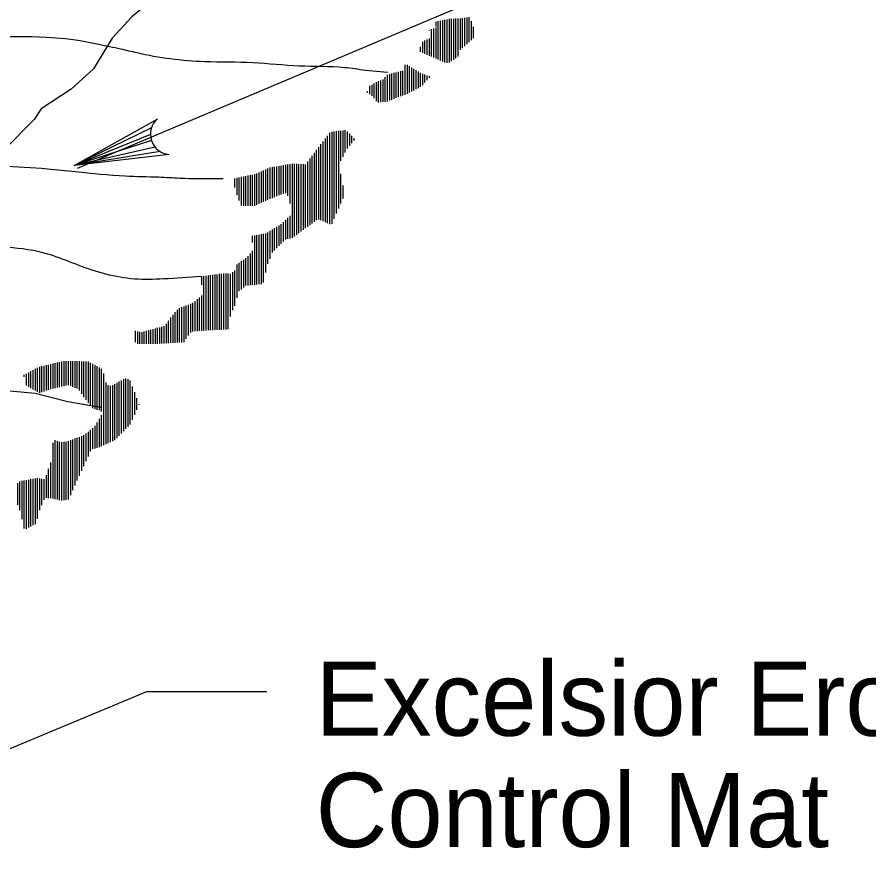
# Model space of a CAD drawing. Extents: x 1083.1 to 1117.1, y 719.4 to 741.4.
# Drawn here: x 1107.903 to 1109.509, y 721.997 to 723.597 of the extents above; entities that cross this region are included whole.
import ezdxf

# ---------------------------------------------------------------- set-up
doc = ezdxf.new("R2010")
doc.units = 0
doc.layers.add('ST_Details', color=7, linetype='Continuous')
doc.layers.add('ST_Text', color=7, linetype='Continuous')

msp = doc.modelspace()

# ---------------------------------------------------------------- linework, layer by layer
at = {"layer": 'ST_Details'}
for p, q in [((1108.6886, 723.5872), (1108.6886, 723.5875)), ((1108.6928, 723.5796), (1108.6928, 723.5885)), ((1108.6969, 723.5175), (1108.6969, 723.5894)), ((1108.7011, 723.5156), (1108.7011, 723.5904)), ((1108.7053, 723.5138), (1108.7053, 723.5913)), ((1108.7094, 723.512), (1108.7094, 723.5922)), ((1108.7136, 723.511), (1108.7136, 723.5931)), ((1108.7178, 723.512), (1108.7178, 723.594)), ((1108.7219, 723.514), (1108.7219, 723.5942)), ((1108.7261, 723.517), (1108.7261, 723.5944)), ((1108.7303, 723.5202), (1108.7303, 723.5945)), ((1108.7344, 723.5232), (1108.7344, 723.5948)), ((1108.7386, 723.5354), (1108.7386, 723.595)), ((1108.7428, 723.539), (1108.7428, 723.5955)), ((1108.7469, 723.5428), (1108.7469, 723.596)), ((1108.7511, 723.5465), (1108.7511, 723.5965)), ((1108.7553, 723.5503), (1108.7553, 723.597)), ((1108.7594, 723.554), (1108.7594, 723.5899)), ((1108.6803, 723.5721), (1108.6803, 723.5728)), ((1108.6844, 723.5229), (1108.6844, 723.5744)), ((1108.6886, 723.521), (1108.6886, 723.576)), ((1108.6928, 723.5192), (1108.6928, 723.5777)), ((1108.7636, 723.5578), (1108.7636, 723.5789)), ((1108.6719, 723.5283), (1108.6719, 723.5532)), ((1108.6761, 723.5265), (1108.6761, 723.555)), ((1108.6803, 723.5246), (1108.6803, 723.557)), ((1108.6636, 723.5319), (1108.6636, 723.5415)), ((1108.6678, 723.5301), (1108.6678, 723.5505)), ((1108.7386, 723.5263), (1108.7386, 723.5263)), ((1108.6345, 723.4511), (1108.6345, 723.5072)), ((1108.6386, 723.4526), (1108.6386, 723.5076)), ((1108.6428, 723.4546), (1108.6428, 723.505)), ((1108.5595, 723.4974), (1108.601, 723.4935)), ((1108.6012, 723.4385), (1108.6012, 723.4886)), ((1108.6053, 723.44), (1108.6053, 723.4898)), ((1108.6095, 723.4416), (1108.6095, 723.4908)), ((1108.6137, 723.4433), (1108.6137, 723.492)), ((1108.6178, 723.4449), (1108.6178, 723.493)), ((1108.622, 723.4465), (1108.622, 723.4941)), ((1108.6262, 723.448), (1108.6262, 723.4953)), ((1108.6303, 723.4495), (1108.6303, 723.4963)), ((1108.6469, 723.457), (1108.6469, 723.5025)), ((1108.6511, 723.4591), (1108.6511, 723.5)), ((1108.6553, 723.4615), (1108.6553, 723.4974)), ((1108.6594, 723.4636), (1108.6594, 723.4948)), ((1108.6636, 723.466), (1108.6636, 723.4922)), ((1108.6678, 723.4693), (1108.6678, 723.4905)), ((1108.6719, 723.4738), (1108.6719, 723.4889)), ((1108.6761, 723.4784), (1108.6761, 723.4874)), ((1108.5762, 723.4445), (1108.5762, 723.4721)), ((1108.5803, 723.4388), (1108.5803, 723.4745)), ((1108.5845, 723.4365), (1108.5845, 723.4763)), ((1108.5887, 723.437), (1108.5887, 723.478)), ((1108.5928, 723.4375), (1108.5928, 723.4796)), ((1108.597, 723.4379), (1108.597, 723.484)), ((1108.6803, 723.483), (1108.6803, 723.4858)), ((1108.5637, 723.455), (1108.5637, 723.4577)), ((1108.5678, 723.452), (1108.5678, 723.4675)), ((1108.572, 723.449), (1108.572, 723.4698)), ((1108.156, 723.3883), (1108.0104, 723.3178)), ((1108.1543, 723.376), (1108.0104, 723.3178)), ((1108.4925, 723.2071), (1108.4925, 723.3791)), ((1108.4967, 723.2078), (1108.4967, 723.3813)), ((1108.5008, 723.2173), (1108.5008, 723.3818)), ((1108.505, 723.2268), (1108.505, 723.3823)), ((1108.5092, 723.2363), (1108.5092, 723.3828)), ((1108.5133, 723.3262), (1108.5133, 723.3832)), ((1108.5175, 723.3341), (1108.5175, 723.3836)), ((1108.5217, 723.342), (1108.5217, 723.3841)), ((1108.5258, 723.3494), (1108.5258, 723.3815)), ((1108.53, 723.3545), (1108.53, 723.3775)), ((1108.1562, 723.3648), (1108.0104, 723.3178)), ((1108.48, 723.2127), (1108.48, 723.363)), ((1108.4842, 723.2108), (1108.4842, 723.3684)), ((1108.4883, 723.209), (1108.4883, 723.3738)), ((1108.5342, 723.3598), (1108.5342, 723.3734)), ((1108.5383, 723.365), (1108.5383, 723.3693)), ((1108.1633, 723.352), (1108.0104, 723.3178)), ((1108.1723, 723.344), (1108.0104, 723.3178)), ((1108.4675, 723.2144), (1108.4675, 723.3469)), ((1108.4717, 723.2156), (1108.4717, 723.3523)), ((1108.4758, 723.2144), (1108.4758, 723.3576)), ((1108.4551, 723.2052), (1108.4551, 723.3305)), ((1108.4592, 723.2082), (1108.4592, 723.336)), ((1108.4633, 723.2113), (1108.4633, 723.3415)), ((1108.3718, 723.2508), (1108.3718, 723.3102)), ((1108.3759, 723.2526), (1108.3759, 723.312)), ((1108.3801, 723.2545), (1108.3801, 723.3135)), ((1108.3843, 723.2562), (1108.3843, 723.3142)), ((1108.3884, 723.258), (1108.3884, 723.315)), ((1108.3926, 723.2599), (1108.3926, 723.3157)), ((1108.3968, 723.2616), (1108.3968, 723.3165)), ((1108.4009, 723.2628), (1108.4009, 723.3172)), ((1108.4051, 723.264), (1108.4051, 723.3179)), ((1108.4093, 723.2651), (1108.4093, 723.3186)), ((1108.4134, 723.2605), (1108.4134, 723.3194)), ((1108.4176, 723.2457), (1108.4176, 723.32)), ((1108.4218, 723.1811), (1108.4218, 723.3207)), ((1108.4259, 723.1838), (1108.4259, 723.3205)), ((1108.4301, 723.1868), (1108.4301, 723.3204)), ((1108.4343, 723.1899), (1108.4343, 723.3202)), ((1108.4384, 723.193), (1108.4384, 723.32)), ((1108.4426, 723.196), (1108.4426, 723.3199)), ((1108.4468, 723.1991), (1108.4468, 723.3197)), ((1108.4509, 723.2021), (1108.4509, 723.3251)), ((1108.3176, 723.2614), (1108.3176, 723.2942)), ((1108.3218, 723.2516), (1108.3218, 723.295)), ((1108.3259, 723.2419), (1108.3259, 723.2959)), ((1108.3301, 723.2412), (1108.3301, 723.2968)), ((1108.3343, 723.2412), (1108.3343, 723.2976)), ((1108.3384, 723.2413), (1108.3384, 723.2985)), ((1108.3426, 723.2413), (1108.3426, 723.2994)), ((1108.3468, 723.2413), (1108.3468, 723.3002)), ((1108.3509, 723.2416), (1108.3509, 723.3011)), ((1108.3551, 723.2435), (1108.3551, 723.3025)), ((1108.3593, 723.2453), (1108.3593, 723.3044)), ((1108.3634, 723.2471), (1108.3634, 723.3064)), ((1108.3676, 723.249), (1108.3676, 723.3082)), ((1108.5133, 723.2457), (1108.5133, 723.302)), ((1108.3134, 723.2762), (1108.3134, 723.2933)), ((1108.5175, 723.2552), (1108.5175, 723.28)), ((1108.4093, 723.1781), (1108.4093, 723.2148)), ((1108.4134, 723.1791), (1108.4134, 723.2189)), ((1108.4176, 723.1801), (1108.4176, 723.2229)), ((1108.3884, 723.1575), (1108.3884, 723.1993)), ((1108.3926, 723.1617), (1108.3926, 723.202)), ((1108.3968, 723.166), (1108.3968, 723.2045)), ((1108.4009, 723.1701), (1108.4009, 723.2071)), ((1108.4051, 723.1743), (1108.4051, 723.2108)), ((1108.3468, 723.1723), (1108.3468, 723.1848)), ((1108.3509, 723.0928), (1108.3509, 723.1855)), ((1108.3551, 723.0932), (1108.3551, 723.1863)), ((1108.3593, 723.0936), (1108.3593, 723.1871)), ((1108.3634, 723.094), (1108.3634, 723.1878)), ((1108.3676, 723.0971), (1108.3676, 723.1886)), ((1108.3718, 723.1155), (1108.3718, 723.1894)), ((1108.3759, 723.1321), (1108.3759, 723.1915)), ((1108.3801, 723.1418), (1108.3801, 723.1941)), ((1108.3843, 723.1534), (1108.3843, 723.1967)), ((1108.3426, 723.092), (1108.3426, 723.1516)), ((1108.3468, 723.0924), (1108.3468, 723.1569)), ((1108.3218, 723.0805), (1108.3218, 723.1338)), ((1108.3259, 723.084), (1108.3259, 723.137)), ((1108.3301, 723.0875), (1108.3301, 723.1399)), ((1108.3343, 723.091), (1108.3343, 723.1429)), ((1108.3384, 723.0915), (1108.3384, 723.1464)), ((1108.3134, 723.0532), (1108.3134, 723.1193)), ((1108.3176, 723.068), (1108.3176, 723.1307)), ((1108.2468, 723.1075), (1108.2468, 723.1077)), ((1108.251, 723.0923), (1108.251, 723.1083)), ((1108.2552, 723.0064), (1108.2552, 723.1089)), ((1108.2593, 723.0067), (1108.2593, 723.1095)), ((1108.2635, 723.0069), (1108.2635, 723.11)), ((1108.2677, 723.007), (1108.2677, 723.1106)), ((1108.2718, 723.0073), (1108.2718, 723.1111)), ((1108.276, 723.0075), (1108.276, 723.1118)), ((1108.2801, 723.0077), (1108.2801, 723.1123)), ((1108.2843, 723.0079), (1108.2843, 723.113)), ((1108.2884, 723.008), (1108.2884, 723.1135)), ((1108.2926, 723.0083), (1108.2926, 723.114)), ((1108.2968, 723.0085), (1108.2968, 723.1142)), ((1108.3009, 723.0087), (1108.3009, 723.1138)), ((1108.3051, 723.033), (1108.3051, 723.1133)), ((1108.3093, 723.0449), (1108.3093, 723.1163)), ((1108.251, 723.006), (1108.251, 723.0723)), ((1108.2218, 722.991), (1108.2218, 723.0535)), ((1108.226, 722.997), (1108.226, 723.0551)), ((1108.2302, 723.0029), (1108.2302, 723.0567)), ((1108.2343, 723.0046), (1108.2343, 723.0585)), ((1108.2385, 723.005), (1108.2385, 723.062)), ((1108.2427, 723.0054), (1108.2427, 723.0655)), ((1108.2468, 723.0057), (1108.2468, 723.0688)), ((1108.201, 722.9833), (1108.201, 723.0409)), ((1108.2052, 722.9835), (1108.2052, 723.0457)), ((1108.2093, 722.9837), (1108.2093, 723.0486)), ((1108.2135, 722.984), (1108.2135, 723.0502)), ((1108.2177, 722.9844), (1108.2177, 723.0519)), ((1108.1885, 722.9826), (1108.1885, 723.0249)), ((1108.1927, 722.9829), (1108.1927, 723.0309)), ((1108.1968, 722.983), (1108.1968, 723.036)), ((1108.126, 722.9842), (1108.126, 723.0057)), ((1108.1468, 722.9815), (1108.1468, 723.0057)), ((1108.151, 722.9815), (1108.151, 723.0068)), ((1108.1552, 722.9816), (1108.1552, 723.0079)), ((1108.1593, 722.9816), (1108.1593, 723.009)), ((1108.1635, 722.9816), (1108.1635, 723.01)), ((1108.1677, 722.9816), (1108.1677, 723.0112)), ((1108.1718, 722.9818), (1108.1718, 723.0123)), ((1108.176, 722.982), (1108.176, 723.0134)), ((1108.1802, 722.9822), (1108.1802, 723.0145)), ((1108.1843, 722.9824), (1108.1843, 723.0189)), ((1108.1302, 722.981), (1108.1302, 723.0047)), ((1108.1343, 722.981), (1108.1343, 723.0038)), ((1108.1385, 722.9812), (1108.1385, 723.0035)), ((1108.1427, 722.9813), (1108.1427, 723.0045)), ((1107.9581, 722.893), (1107.9581, 722.9409)), ((1107.9623, 722.8944), (1107.9623, 722.9419)), ((1107.9664, 722.8958), (1107.9664, 722.9429)), ((1107.9706, 722.8968), (1107.9706, 722.944)), ((1107.9748, 722.8978), (1107.9748, 722.945)), ((1107.9789, 722.8988), (1107.9789, 722.946)), ((1107.9831, 722.8997), (1107.9831, 722.947)), ((1107.9873, 722.9006), (1107.9873, 722.948)), ((1107.9914, 722.9016), (1107.9914, 722.9489)), ((1107.9956, 722.9026), (1107.9956, 722.9489)), ((1107.9998, 722.9035), (1107.9998, 722.9487)), ((1108.0039, 722.902), (1108.0039, 722.9486)), ((1108.0081, 722.9003), (1108.0081, 722.9485)), ((1108.0123, 722.8986), (1108.0123, 722.9485)), ((1108.0164, 722.897), (1108.0164, 722.9484)), ((1108.0206, 722.8933), (1108.0206, 722.9483)), ((1108.0248, 722.8871), (1108.0248, 722.9482)), ((1108.0289, 722.881), (1108.0289, 722.948)), ((1108.0331, 722.8755), (1108.0331, 722.948)), ((1108.0373, 722.8703), (1108.0373, 722.9477)), ((1108.0414, 722.8653), (1108.0414, 722.9455)), ((1108.0456, 722.8601), (1108.0456, 722.9433)), ((1108.0498, 722.8583), (1108.0498, 722.941)), ((1107.9207, 722.9027), (1107.9207, 722.9249)), ((1107.9248, 722.9003), (1107.9248, 722.9272)), ((1107.9289, 722.898), (1107.9289, 722.9295)), ((1107.9331, 722.8955), (1107.9331, 722.9317)), ((1107.9373, 722.8931), (1107.9373, 722.934)), ((1107.9414, 722.8908), (1107.9414, 722.9363)), ((1107.9456, 722.8888), (1107.9456, 722.9378)), ((1107.9498, 722.8901), (1107.9498, 722.9389)), ((1107.9539, 722.8915), (1107.9539, 722.9399)), ((1108.0539, 722.8571), (1108.0539, 722.9389)), ((1108.0581, 722.856), (1108.0581, 722.9366)), ((1108.0623, 722.8535), (1108.0623, 722.9344)), ((1108.0664, 722.7901), (1108.0664, 722.9254)), ((1107.9165, 722.9193), (1107.9165, 722.9227)), ((1108.0706, 722.7921), (1108.0706, 722.9086)), ((1108.0956, 722.808), (1108.0956, 722.91)), ((1108.0998, 722.8123), (1108.0998, 722.9123)), ((1108.1039, 722.8165), (1108.1039, 722.9146)), ((1108.108, 722.8208), (1108.108, 722.9161)), ((1108.1122, 722.8251), (1108.1122, 722.9146)), ((1108.1163, 722.8295), (1108.1163, 722.912)), ((1108.0748, 722.794), (1108.0748, 722.9036)), ((1108.0789, 722.796), (1108.0789, 722.902)), ((1108.0831, 722.7978), (1108.0831, 722.9032)), ((1108.0873, 722.7998), (1108.0873, 722.9055)), ((1108.0914, 722.8036), (1108.0914, 722.9078)), ((1108.1205, 722.8383), (1108.1205, 722.901)), ((1108.1247, 722.8475), (1108.1247, 722.8899)), ((1108.1288, 722.8567), (1108.1288, 722.8788)), ((1108.133, 722.866), (1108.133, 722.8678)), ((1108.0623, 722.7883), (1108.0623, 722.8465)), ((1108.0539, 722.785), (1108.0539, 722.8331)), ((1108.0581, 722.7863), (1108.0581, 722.8398)), ((1108.0331, 722.7812), (1108.0331, 722.8124)), ((1108.0373, 722.782), (1108.0373, 722.8156)), ((1108.0414, 722.7826), (1108.0414, 722.8189)), ((1108.0456, 722.7835), (1108.0456, 722.8221)), ((1108.0498, 722.7841), (1108.0498, 722.8265)), ((1107.9748, 722.6887), (1107.9748, 722.7995)), ((1107.9789, 722.6877), (1107.9789, 722.798)), ((1107.9831, 722.6866), (1107.9831, 722.7965)), ((1107.9914, 722.6865), (1107.9914, 722.7963)), ((1107.9956, 722.6872), (1107.9956, 722.7968)), ((1107.9998, 722.6879), (1107.9998, 722.798)), ((1108.0039, 722.696), (1108.0039, 722.7995)), ((1108.0081, 722.7052), (1108.0081, 722.801)), ((1108.0123, 722.7143), (1108.0123, 722.8025)), ((1108.0164, 722.7234), (1108.0164, 722.8041)), ((1108.0206, 722.7325), (1108.0206, 722.8056)), ((1108.0248, 722.7417), (1108.0248, 722.8071)), ((1108.0289, 722.7508), (1108.0289, 722.8091)), ((1107.9706, 722.6897), (1107.9706, 722.7945)), ((1107.9873, 722.6859), (1107.9873, 722.7959)), ((1108.0331, 722.7599), (1108.0331, 722.7812)), ((1108.0373, 722.769), (1108.0373, 722.782)), ((1108.0414, 722.7782), (1108.0414, 722.7826)), ((1107.9664, 722.6902), (1107.9664, 722.7575)), ((1107.9581, 722.6909), (1107.9581, 722.7336)), ((1107.9623, 722.6905), (1107.9623, 722.7455)), ((1107.904, 722.6777), (1107.904, 722.7183)), ((1107.9082, 722.6677), (1107.9082, 722.722)), ((1107.9123, 722.6504), (1107.9123, 722.7228)), ((1107.9165, 722.633), (1107.9165, 722.7235)), ((1107.9207, 722.6325), (1107.9207, 722.7244)), ((1107.9248, 722.6347), (1107.9248, 722.7251)), ((1107.9289, 722.637), (1107.9289, 722.7259)), ((1107.9331, 722.6392), (1107.9331, 722.7267)), ((1107.9373, 722.6414), (1107.9373, 722.7275)), ((1107.9414, 722.6514), (1107.9414, 722.7278)), ((1107.9456, 722.6674), (1107.9456, 722.7272)), ((1107.9498, 722.6772), (1107.9498, 722.7267)), ((1107.9539, 722.6869), (1107.9539, 722.726))]:
    msp.add_line(p, q, dxfattribs=at)
for points in [[(1108.8059, 724.3275), (1108.7346, 724.2872), (1108.6921, 724.2617), (1108.6701, 724.2321), (1108.6434, 724.1676), (1108.6131, 724.1284), (1108.5522, 724.0713), (1108.5, 723.9771), (1108.4597, 723.9105), (1108.3613, 723.851), (1108.3054, 723.7939), (1108.2514, 723.7272), (1108.1872, 723.6541), (1108.1193, 723.598), (1108.0823, 723.5578), (1108.0469, 723.4996), (1108.0046, 723.4615), (1107.9485, 723.4244), (1107.935, 723.4043), (1107.8775, 723.346)], [(1108.0168, 723.3126), (1108.9788, 723.719), (1109.2207, 723.719)], [(1108.1898, 723.3384), (1108.0104, 723.3178), (1108.168, 723.4058)], [(1108.06, 722.8614), (1107.9984, 722.8718), (1107.9367, 722.8875), (1107.8478, 722.8958)], [(1107.3588, 721.9968), (1108.1472, 722.3259), (1108.374, 722.3259)]]:
    msp.add_lwpolyline(points, dxfattribs=at)
msp.add_arc((1108.1924, 723.3765), 0.0382, 129.9568, 265.783, dxfattribs=at)
for points in [[(1105.4163, 723.7798), (1105.5138, 723.7736), (1105.5651, 723.7695), (1105.6233, 723.7611), (1105.7088, 723.7486), (1105.7463, 723.7466), (1105.8369, 723.7446), (1105.8626, 723.7426), (1105.9224, 723.7364), (1105.9891, 723.7333), (1106.0592, 723.7293), (1106.1652, 723.7231), (1106.2508, 723.7063), (1106.3108, 723.697), (1106.403, 723.6865), (1106.5466, 723.6805), (1106.6323, 723.6648), (1106.7382, 723.6618), (1106.8578, 723.6621), (1106.9621, 723.6549), (1107.0682, 723.6425), (1107.1555, 723.6236), (1107.2274, 723.6058), (1107.3283, 723.5922), (1107.4258, 723.5882), (1107.5472, 723.5842), (1107.6566, 723.5739), (1107.8498, 723.5605), (1107.9574, 723.5597), (1108.031, 723.5514), (1108.0568, 723.5461), (1108.0978, 723.5377), (1108.1285, 723.5304), (1108.2569, 723.5137), (1108.3474, 723.5118), (1108.4348, 723.5056), (1108.5202, 723.5026), (1108.5595, 723.4974)], [(1108.2507, 723.108), (1108.1789, 723.1036), (1108.1242, 723.1035), (1108.0181, 723.1296), (1107.97, 723.1476), (1107.8948, 723.1622), (1107.8024, 723.1641), (1107.7033, 723.1745), (1107.5748, 723.1944), (1107.4381, 723.2036), (1107.3373, 723.2139), (1107.2637, 723.219), (1107.1869, 723.2085), (1107.0912, 723.2134), (1106.9801, 723.211), (1106.9083, 723.2184), (1106.7902, 723.2414), (1106.6874, 723.2687), (1106.6191, 723.2664), (1106.5353, 723.2662), (1106.4035, 723.2871), (1106.2718, 723.307), (1106.1197, 723.314), (1106.0461, 723.3234), (1105.9348, 723.3517), (1105.8356, 723.3631), (1105.7518, 723.365), (1105.6543, 723.3712), (1105.5843, 723.3816), (1105.4644, 723.4015), (1105.3703, 723.4108), (1105.2336, 723.4265), (1105.0983, 723.4441), (1105.0538, 723.4504), (1105.0385, 723.4503)], [(1106.8368, 723.4393), (1106.8908, 723.4286), (1107.0585, 723.4078), (1107.1887, 723.3827), (1107.2948, 723.3575), (1107.3478, 723.3492), (1107.4178, 723.3452), (1107.5222, 723.339), (1107.6059, 723.3339), (1107.6658, 723.333), (1107.7907, 723.3205), (1107.8727, 723.3165), (1107.9599, 723.3114), (1108.0129, 723.3062), (1108.1069, 723.2979), (1108.1702, 723.2959), (1108.2095, 723.2939), (1108.2796, 723.293), (1108.2915, 723.293)]]:
    msp.add_spline(points, degree=3, dxfattribs=at)

# ---------------------------------------------------------------- texts
at = {"layer": 'ST_Text'}
for s, p in [('Excelsior Erosion', (1108.4658, 722.2423)), ('Control Mat', (1108.4658, 722.0323))]:
    msp.add_text(s, height=0.14, dxfattribs=at).set_placement(p)

doc.saveas('drawing.dxf')
